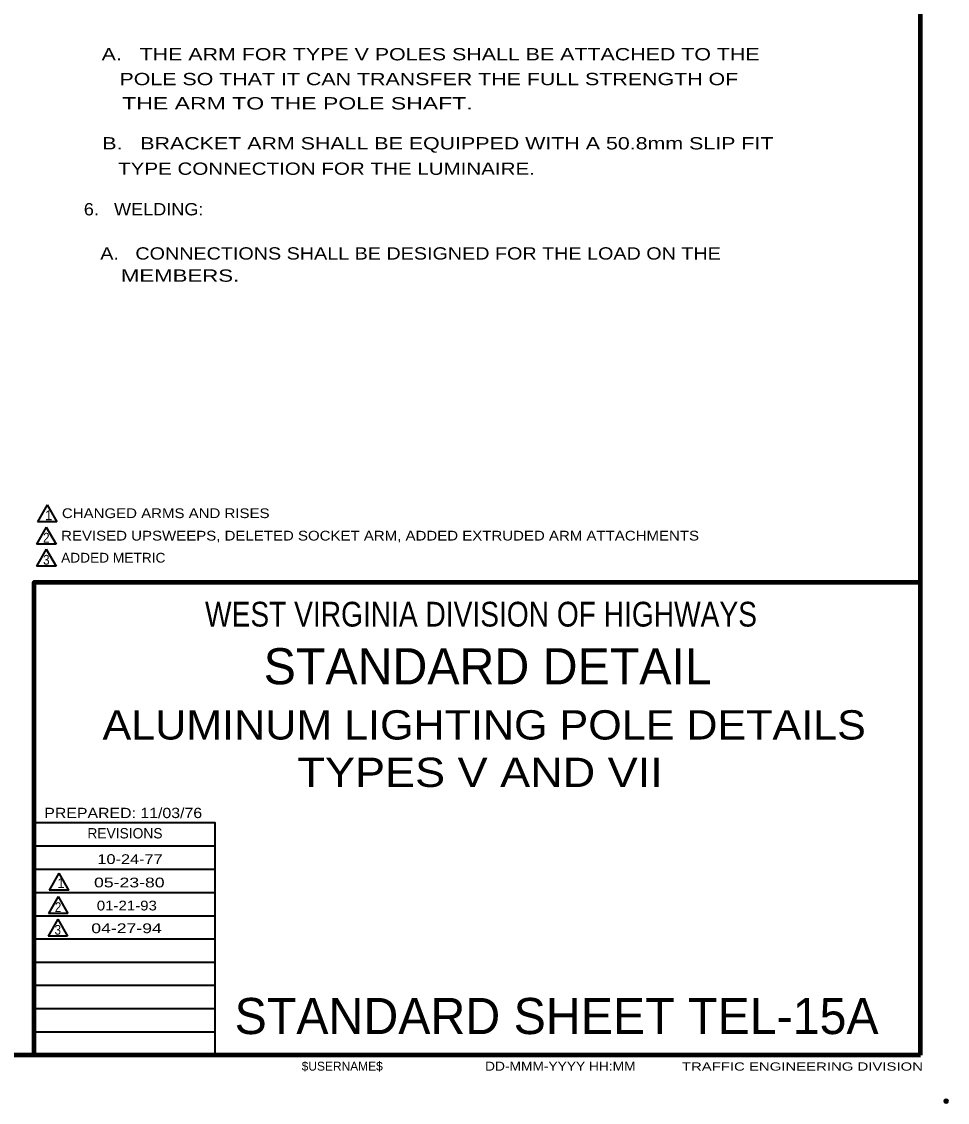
# Model space of a CAD drawing. Extents: x -20 to 693, y -19 to 435.
# Drawn here: x 503.5 to 693.2, y -18.7 to 202.7 of the extents above; entities that cross this region are included whole.
import ezdxf
from ezdxf.enums import TextEntityAlignment as Align

# ---------------------------------------------------------------- set-up
doc = ezdxf.new("R2010")
doc.units = 0
doc.header["$PDMODE"] = 32
doc.header["$PDSIZE"] = 0.5
doc.layers.add('1', color=7, linetype='Continuous', lineweight=53)
doc.layers.add('61', color=7, linetype='Continuous', lineweight=35)

msp = doc.modelspace()

# ---------------------------------------------------------------- linework, layer by layer
at = {"layer": '1', "lineweight": 158}
for q in [(687.723, 429.353), (687.723, 87.853), (28.056, -9.063)]:
    msp.add_line((687.723, -9.063), q, dxfattribs=at)
at = {"layer": '1', "lineweight": 13}
msp.add_line((687.723, -9.063), (687.723, 429.353), dxfattribs=at)
at = {"layer": '1', "lineweight": 35}
for p, q in [((508.719, 103.726), (506.719, 100.262)), ((508.719, 103.726), (510.719, 100.262)), ((510.719, 100.262), (506.719, 100.262)), ((508.555, 99.129), (506.555, 95.664)), ((508.555, 99.129), (510.555, 95.664)), ((510.555, 95.664), (506.555, 95.664)), ((508.555, 94.608), (506.555, 91.144)), ((508.555, 94.608), (510.555, 91.144)), ((510.555, 91.144), (506.555, 91.144)), ((543.14, 33.77), (506.056, 33.77)), ((543.14, 29.02), (506.056, 29.02)), ((511.131, 28.235), (509.131, 24.771)), ((543.14, 24.187), (506.056, 24.187)), ((510.971, 23.446), (508.971, 19.982)), ((510.971, 23.446), (512.971, 19.982)), ((512.971, 19.982), (508.971, 19.982)), ((543.14, 19.437), (506.056, 19.437)), ((510.906, 18.795), (508.906, 15.331)), ((510.906, 18.795), (512.906, 15.331)), ((543.14, 14.687), (506.056, 14.687)), ((512.906, 15.331), (508.906, 15.331)), ((543.14, 9.937), (506.056, 9.937)), ((543.14, 5.187), (506.056, 5.187)), ((543.14, 0.437), (506.056, 0.437)), ((543.14, -4.313), (506.056, -4.313))]:
    msp.add_line(p, q, dxfattribs=at)
at = {"layer": '1', "lineweight": 158}
msp.add_lwpolyline([(506.056, -9.063), (506.056, 87.853), (687.723, 87.853)], dxfattribs=at)
at = {"layer": '1', "lineweight": 35}
for points in [[(543.14, -9.063), (543.14, 38.52), (506.056, 38.52)], [(511.131, 28.235), (513.131, 24.771), (509.131, 24.771)]]:
    msp.add_lwpolyline(points, dxfattribs=at)
at = {"layer": '1'}
msp.add_point((692.973, -18.48), dxfattribs=at)
at = {"layer": '61', "lineweight": 53}
for q in [(560.473, -9.063), (560.473, -9.063), (560.473, -9.063), (560.723, -9.063), (560.723, -9.063)]:
    msp.add_line((687.723, -9.063), q, dxfattribs=at)

# ---------------------------------------------------------------- texts
at = {"layer": '1'}
for s, height, width, p in [('   A.   THE ARM FOR TYPE V POLES SHALL BE ATTACHED TO THE', 2.52, 1.3, (516.243, 194.787)), ('      POLE SO THAT IT CAN TRANSFER THE FULL STRENGTH OF', 2.52, 1.3, (516.243, 189.702)), ('      THE ARM TO THE POLE SHAFT.', 2.52, 1.4, (516.243, 184.727)), ('   B.   BRACKET ARM SHALL BE EQUIPPED WITH A 50.8mm SLIP FIT', 2.52, 1.3, (516.38, 176.535)), ('      TYPE CONNECTION FOR THE LUMINAIRE.', 2.52, 1.25, (516.243, 171.333)), ('6.   WELDING:', 2.52, 1.1, (516.243, 163.027)), ('   A.   CONNECTIONS SHALL BE DESIGNED FOR THE LOAD ON THE', 2.52, 1.2, (516.243, 153.967)), ('      MEMBERS. ', 2.52, 1.35, (516.243, 149.427)), ('CHANGED ARMS AND RISES', 2, 1.15, (511.754, 100.995)), ('2', 2, 0.9, (507.885, 95.97)), ('REVISED UPSWEEPS, DELETED SOCKET ARM, ADDED EXTRUDED ARM ATTACHMENTS', 2, 1.15, (511.589, 96.397)), ('3', 2, 0.9, (507.885, 91.45)), ('ADDED METRIC', 2, 1.05, (511.589, 91.877)), ('ALUMINUM LIGHTING POLE DETAILS', 6, 1.1, (520.071, 55.623)), ('TYPES V AND VII', 6, 1.15, (560.028, 45.901)), ('PREPARED: 11/03/76', 2.114, 1.15, (508.14, 39.52)), ('2', 2, 0.9, (510.294, 20.276)), ('3', 2, 0.9, (510.229, 15.625)), ('DD-MMM-YYYY HH:MM', 1.833, 1.15, (598.473, -12.23)), ('TRAFFIC ENGINEERING DIVISION', 1.693, 1.35, (638.806, -12.23))]:
    msp.add_text(s, height=height, dxfattribs=dict(at, width=width)).set_placement(p)
for s, height, p in [('1', 2, (508.282, 100.568)), ('REVISIONS', 2.114, (516.973, 35.353)), ('1', 2, (510.805, 25.205)), ('STANDARD SHEET TEL-15A', 7.401, (547.14, -4.73)), ('$USERNAME$', 1.833, (560.89, -12.23))]:
    msp.add_text(s, height=height, dxfattribs=at).set_placement(p)
for s, height, width, p in [('WEST VIRGINIA DIVISION OF HIGHWAYS', 5.074, 0.85, (597.64, 78.77)), ('10-24-77', 2, 1.25, (525.712, 30.116)), ('05-23-80', 2, 1.35, (525.562, 25.326)), ('01-21-93', 2, 1.15, (525.056, 20.6)), ('04-27-94', 2, 1.35, (524.999, 15.949))]:
    msp.add_text(s, height=height, dxfattribs=dict(at, width=width)).set_placement(p, align=Align.CENTER)
msp.add_text('STANDARD DETAIL', height=7.401, dxfattribs=at).set_placement((599.015, 66.937), align=Align.CENTER)

doc.saveas('drawing.dxf')
